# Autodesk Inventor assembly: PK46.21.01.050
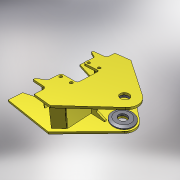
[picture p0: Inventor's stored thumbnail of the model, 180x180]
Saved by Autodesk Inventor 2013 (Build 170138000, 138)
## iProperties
Created: 2005-04
Part Number: PK46.21.01.050
Document SubType Name: Assembly
Designer: salex
Manufacturer: Standard
Standards Organization: Custom
Author: salex
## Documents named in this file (9)
- C:\Product Design Suite 2013 Test Drive\Dynamic Simulation\Workspace\Assy, Chassis, Front\PK46.21.01.050.iam
- C:\Product Design Suite 2013 Test Drive\Dynamic Simulation\Workspace\Assy, Chassis, Front\PK46.21.01.011.ipt
- C:\Product Design Suite 2013 Test Drive\Dynamic Simulation\Workspace\Assy, Chassis, Front\PK46.21.01.012.ipt
- C:\Product Design Suite 2013 Test Drive\Dynamic Simulation\Workspace\Assy, Chassis, Front\PK46.21.01.013.ipt
- C:\Product Design Suite 2013 Test Drive\Dynamic Simulation\Workspace\Assy, Chassis, Front\PK46.21.01.014.ipt
- C:\Product Design Suite 2013 Test Drive\Dynamic Simulation\Workspace\Assy, Chassis, Front\PK46.21.01.015.ipt
- C:\Product Design Suite 2013 Test Drive\Dynamic Simulation\Workspace\Assy, Chassis, Front\PK46.21.01.016.ipt
- C:\Product Design Suite 2013 Test Drive\Dynamic Simulation\Workspace\Assy, Chassis, Front\PK46.21.01.015-02.ipt
- C:\Product Design Suite 2013 Test Drive\Dynamic Simulation\Workspace\Assy, Chassis, Front\PK46.21.01.015-01.ipt
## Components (12 placed, 8 different names)
1. PK46.21.01.011:1 — Совмещение:3, Вставка:2, Угол:2, Заподлицо:3, Совмещение:29, Совмещение:31, Заподлицо:10, Заподлицо:11, Совмещение:37, Совмещение:40
2. PK46.21.01.012:1 — Совмещение:3, Вставка:1, Совмещение:4, Совмещение:5, Угол:1, Совмещение:6, Совмещение:7, Угол:2, Совмещение:10, Совмещение:11, Совмещение:30, Совмещение:33, Совмещение:34, Совмещение:35, Совмещение:38, Заподлицо:9
3. PK46.21.01.013:1 — Вставка:2
4. PK46.21.01.013:2 — Вставка:1
5. PK46.21.01.014:1 — Совмещение:4, Угол:1, Совмещение:6, Совмещение:8
6. PK46.21.01.014:2 — Совмещение:5, Совмещение:9, Совмещение:10
7. PK46.21.01.015:1 — Совмещение:35, Совмещение:36, Совмещение:37
8. PK46.21.01.015:2 — Совмещение:38, Совмещение:39, Совмещение:40
9. PK46.21.01.015-02:1 — Совмещение:7, Совмещение:8, Совмещение:9, Совмещение:11, Заподлицо:3, Совмещение:29, Совмещение:36, Совмещение:39
10. PK46.21.01.016:1 — Совмещение:30, Совмещение:31, Совмещение:32, Заподлицо:9
11. PK46.21.01.015-01:3 — Заподлицо:11, Заподлицо:12, Совмещение:34
12. PK46.21.01.015-01:4 — Совмещение:32, Совмещение:33, Заподлицо:10, Заподлицо:12
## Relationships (30: Mate 21, Flush 5, Insert 2, Angle 2)
- Совмещение:3 [Mate]: PK46.21.01.011:1 ↔ PK46.21.01.012:1
- Вставка:1 [Insert]: PK46.21.01.012:1 ↔ PK46.21.01.013:2
- Вставка:2 [Insert]: PK46.21.01.011:1 ↔ PK46.21.01.013:1
- Совмещение:4 [Mate]: PK46.21.01.012:1 ↔ PK46.21.01.014:1
- Совмещение:5 [Mate]: PK46.21.01.012:1 ↔ PK46.21.01.014:2
- Угол:1 [Angle]: PK46.21.01.012:1 ↔ PK46.21.01.014:1
- Совмещение:6 [Mate]: PK46.21.01.012:1 ↔ PK46.21.01.014:1
- Совмещение:7 [Mate]: PK46.21.01.012:1 ↔ PK46.21.01.015-02:1
- Совмещение:8 [Mate]: PK46.21.01.014:1 ↔ PK46.21.01.015-02:1
- Совмещение:9 [Mate]: PK46.21.01.014:2 ↔ PK46.21.01.015-02:1
- Угол:2 [Angle]: PK46.21.01.011:1 ↔ PK46.21.01.012:1
- Совмещение:10 [Mate]: PK46.21.01.012:1 ↔ PK46.21.01.014:2
- Совмещение:11 [Mate]: PK46.21.01.012:1 ↔ PK46.21.01.015-02:1
- Заподлицо:3 [Flush]: PK46.21.01.011:1 ↔ PK46.21.01.015-02:1
- Совмещение:29 [Mate]: PK46.21.01.011:1 ↔ PK46.21.01.015-02:1
- Совмещение:30 [Mate]: PK46.21.01.012:1 ↔ PK46.21.01.016:1
- Совмещение:31 [Mate]: PK46.21.01.011:1 ↔ PK46.21.01.016:1
- Совмещение:32 [Mate]: PK46.21.01.016:1 ↔ PK46.21.01.015-01:4
- Совмещение:33 [Mate]: PK46.21.01.012:1 ↔ PK46.21.01.015-01:4
- Заподлицо:10 [Flush]: PK46.21.01.011:1 ↔ PK46.21.01.015-01:4
- Заподлицо:11 [Flush]: PK46.21.01.011:1 ↔ PK46.21.01.015-01:3
- Заподлицо:12 [Flush]: PK46.21.01.015-01:3 ↔ PK46.21.01.015-01:4
- Совмещение:34 [Mate]: PK46.21.01.012:1 ↔ PK46.21.01.015-01:3
- Совмещение:35 [Mate]: PK46.21.01.012:1 ↔ PK46.21.01.015:1
- Совмещение:36 [Mate]: PK46.21.01.015:1 ↔ PK46.21.01.015-02:1
- Совмещение:37 [Mate]: PK46.21.01.011:1 ↔ PK46.21.01.015:1
- Совмещение:38 [Mate]: PK46.21.01.012:1 ↔ PK46.21.01.015:2
- Совмещение:39 [Mate]: PK46.21.01.015:2 ↔ PK46.21.01.015-02:1
- Совмещение:40 [Mate]: PK46.21.01.011:1 ↔ PK46.21.01.015:2
- Заподлицо:9 [Flush]: PK46.21.01.012:1 ↔ PK46.21.01.016:1
